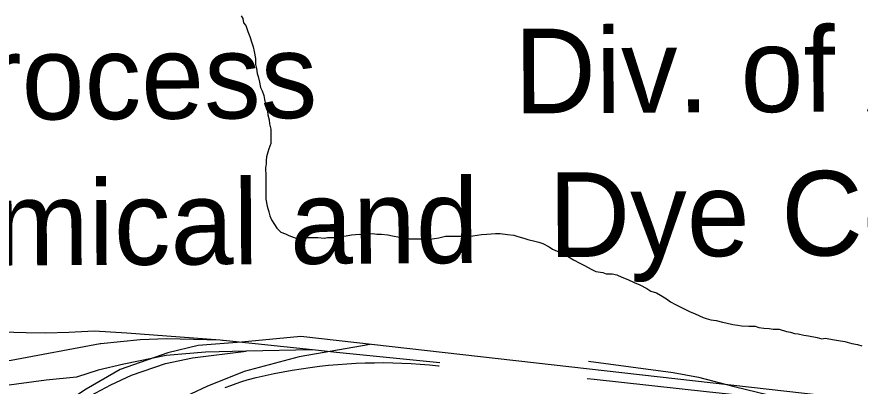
# Model space of a CAD drawing. Extents: x 3313442 to 3351311, y 721974 to 747360.
# Drawn here: x 3326114 to 3326941, y 728065 to 728427 of the extents above; entities that cross this region are included whole.
import ezdxf

# ---------------------------------------------------------------- set-up
doc = ezdxf.new("R2010")
doc.units = 0
for name, color, linetype in [('V-BLDG-IDEN', 7, 'Continuous'), ('V-RAIL-TRAK', 7, 'Continuous'), ('V-ROAD-CNTR', 7, 'Continuous'), ('V-TOPO-SHOR', 7, 'Continuous')]:
    doc.layers.add(name, color=color, linetype=linetype)

msp = doc.modelspace()

# ---------------------------------------------------------------- linework, layer by layer
at = {"layer": 'V-RAIL-TRAK'}
msp.add_line((3326404.1, 728100.63), (3326319.87, 728109.55), dxfattribs=at)
for points in [[(3326319.87, 728109.55), (3326313.59, 728110.02), (3326222.22, 728116.89), (3326206.08, 728118.08), (3326189.94, 728118.85), (3326165.29, 728117.63), (3326142.72, 728117.02), (3326123.27, 728117.41), (3326050.82, 728119.13), (3325836.27, 728133.16), (3325592.99, 728152.23)], [(3326195.84, 728106.45), (3326108.53, 728090.3), (3326083.03, 728087.43), (3326066.88, 728086.55), (3326035.01, 728088.09), (3325588.6, 728124.6)], [(3326319.87, 728109.55), (3326315.96, 728109.96), (3326313.59, 728110.02), (3326261.32, 728111.31), (3326235.02, 728110.52), (3326196.68, 728106.53), (3326195.84, 728106.45)], [(3326404.1, 728100.63), (3326339.26, 728099.19), (3326299.33, 728098.31), (3326260.79, 728094.95), (3326219.29, 728086.46), (3326193.82, 728080.84), (3326172.6, 728073.8), (3326142.89, 728071.02), (3326101.86, 728065.42), (3326053.88, 728061.48), (3325992.83, 728064.54), (3325858.65, 728073.07), (3325585.99, 728094.07)], [(3325985.79, 727363.24), (3326009.02, 727591.42), (3326017.46, 727674.76), (3326022.43, 727718.19), (3326022.46, 727718.49), (3326028.56, 727775.9), (3326035.27, 727828.42), (3326038.78, 727849.29), (3326044.81, 727873.66), (3326053.97, 727900.91), (3326066.03, 727928.53), (3326075.5, 727945.01), (3326093.14, 727971.34), (3326115.75, 727997.83), (3326128.71, 728011.17), (3326153.98, 728034.11), (3326177.11, 728050.67), (3326206.24, 728066.33), (3326226.62, 728075.66), (3326260.06, 728087.15), (3326286.4, 728092.69), (3326339.26, 728099.19)], [(3326528.99, 728087.87), (3326427.65, 728098.14), (3326404.1, 728100.63)], [(3326674.99, 728089.54), (3326716.53, 728084.02), (3326757.88, 728078.31), (3326782.9, 728073.71), (3326817.76, 728064.83), (3326851.67, 728056.54), (3326877.05, 728050.35)], [(3326340.13, 728071.24), (3326348.88, 728073.45), (3326357.66, 728075.5), (3326366.47, 728077.4), (3326375.32, 728079.15), (3326384.2, 728080.74), (3326393.1, 728082.17), (3326402.02, 728083.45), (3326410.97, 728084.58), (3326419.94, 728085.54), (3326428.92, 728086.35), (3326437.91, 728087.01), (3326446.92, 728087.51), (3326455.93, 728087.85), (3326464.94, 728088.03), (3326473.96, 728088.06), (3326482.97, 728087.92), (3326491.99, 728087.63), (3326500.99, 728087.19), (3326509.99, 728086.58), (3326518.98, 728085.82), (3326527.95, 728084.9), (3326528.45, 728084.85)], [(3326318.62, 728063.56), (3326324.04, 728065.66), (3326329.5, 728067.66), (3326335, 728069.56), (3326340.13, 728071.24)], [(3326983.36, 728039.07), (3326877.05, 728050.35), (3326790.61, 728059.52), (3326680.58, 728071.53), (3326673.55, 728072.22)]]:
    msp.add_lwpolyline(points, dxfattribs=at)
at = {"layer": 'V-ROAD-CNTR'}
for points in [[(3327025.43, 728042.18), (3326392.8, 728113.66), (3326334.7, 728108.13), (3326292.14, 728104.74), (3326262.39, 728097.61), (3326215.45, 728081.43), (3326182.31, 728062.11), (3326160.18, 728047.83), (3326133.05, 728026.27), (3326105.61, 727995.37), (3326076.21, 727955.76), (3326065.98, 727932.84), (3326051.28, 727900.09), (3326042.13, 727864.83), (3326032.84, 727808.33), (3326009.58, 727586.2), (3325984.72, 727366.08)], [(3326460.83, 728105.98), (3326391.24, 728093.81), (3326337.19, 728079.55), (3326300.61, 728064.57), (3326254.46, 728043.15), (3326225.23, 728021.97), (3326192.21, 727991.97), (3326160.52, 727958.01), (3326125.37, 727903.1), (3326110.13, 727866.88), (3326095.45, 727827.5), (3326093.16, 727766.49), (3326082.4, 727675.66), (3326045.28, 727366.17)]]:
    msp.add_lwpolyline(points, dxfattribs=at)
at = {"layer": 'V-TOPO-SHOR'}
for points in [[(3326334.17, 728428.44), (3326335.86, 728425.59), (3326336.41, 728421.62), (3326338.67, 728418.78), (3326339.8, 728415.93), (3326340.92, 728413.09), (3326342.61, 728407.98), (3326344.85, 728401.73), (3326345.98, 728397.76), (3326347.09, 728393.21), (3326348.21, 728386.4), (3326348.19, 728380.73), (3326349.31, 728376.76), (3326349.86, 728371.65), (3326350.98, 728368.81), (3326352.09, 728363.13), (3326353.21, 728358.02), (3326354.9, 728354.61), (3326356.59, 728350.07), (3326357.14, 728346.09), (3326358.26, 728341.55), (3326358.82, 728337.58), (3326359.94, 728334.74), (3326360.5, 728331.33), (3326361.61, 728326.22), (3326362.17, 728322.25), (3326363.29, 728317.14), (3326363.27, 728312.6), (3326363.25, 728307.49), (3326363.23, 728302.95), (3326361.52, 728297.85), (3326360.37, 728294.45), (3326359.22, 728289.92), (3326358.64, 728286.52), (3326358.63, 728283.11), (3326358.05, 728279.14), (3326358.59, 728271.2), (3326358.57, 728265.53), (3326358.54, 728257.02), (3326358.52, 728251.91), (3326358.51, 728248.51), (3326359.62, 728241.69), (3326361.3, 728236.02), (3326362.42, 728232.04), (3326364.11, 728228.06), (3326366.93, 728223.51), (3326369.19, 728220.1), (3326373.15, 728216.12), (3326377.68, 728214.4), (3326381.08, 728212.68)], [(3326381.08, 728212.68), (3326386.18, 728210.97), (3326389.01, 728209.82), (3326394.12, 728210.37), (3326398.09, 728210.93), (3326403.77, 728210.9), (3326409.44, 728210.89), (3326415.68, 728210.3), (3326419.08, 728210.85), (3326425.89, 728210.83), (3326430.43, 728211.38), (3326437.24, 728212.49), (3326442.35, 728213.61), (3326450.3, 728214.15), (3326453.7, 728213.57), (3326458.24, 728214.12), (3326463.35, 728214.67), (3326467.32, 728214.09), (3326471.86, 728214.08), (3326478.1, 728213.48), (3326482.63, 728212.33), (3326489.44, 728211.18), (3326493.4, 728210.59), (3326499.07, 728209.44), (3326503.61, 728209.43), (3326508.15, 728209.41), (3326513.83, 728209.39), (3326519.5, 728209.37), (3326528.01, 728210.48), (3326534.83, 728212.16), (3326540.5, 728212.14), (3326546.74, 728212.11), (3326550.71, 728212.1), (3326556.95, 728212.08), (3326561.49, 728212.63), (3326570.01, 728213.73), (3326575.11, 728214.29)], [(3326575.11, 728214.29), (3326583.62, 728214.82), (3326588.17, 728214.81), (3326595.54, 728213.65), (3326601.77, 728213.06), (3326605.74, 728211.91), (3326611.41, 728210.19), (3326615.38, 728209.04), (3326622.18, 728207.31), (3326626.15, 728206.17), (3326630.11, 728205.02), (3326636.34, 728201.59), (3326639.74, 728199.31), (3326646.54, 728196.45), (3326649.37, 728194.74), (3326654.46, 728192.45), (3326660.13, 728189.03), (3326666.36, 728185.6), (3326670.89, 728183.32), (3326677.68, 728179.89), (3326682.21, 728177.61), (3326689.02, 728176.45), (3326692.42, 728175.3), (3326698.09, 728175.28), (3326702.63, 728174.13), (3326707.72, 728171.84), (3326713.39, 728169.56), (3326719.62, 728166.7), (3326725.29, 728164.41), (3326732.08, 728160.98), (3326736.04, 728158.13), (3326741.71, 728156.41), (3326745.68, 728154.13), (3326751.34, 728150.7), (3326755.3, 728147.85), (3326760.39, 728145), (3326764.36, 728143.28), (3326769.46, 728140.43), (3326773.99, 728138.14), (3326779.65, 728135.85), (3326787.58, 728132.42), (3326790.42, 728131.28), (3326794.95, 728130.13), (3326800.05, 728129.54), (3326806.29, 728127.82), (3326809.69, 728127.24), (3326816.49, 728125.52), (3326821.6, 728124.93), (3326825, 728124.35), (3326832.37, 728123.76), (3326838.61, 728123.74), (3326842.02, 728122.59), (3326847.12, 728122.01), (3326852.22, 728121.42), (3326856.19, 728120.84), (3326861.86, 728120.82), (3326869.23, 728118.53), (3326873.2, 728117.95), (3326877.17, 728116.8), (3326880.57, 728116.22), (3326886.24, 728115.06), (3326890.78, 728114.48), (3326899.28, 728112.75), (3326903.81, 728111.6), (3326907.22, 728112.15)], [(3326907.22, 728112.15), (3326916.29, 728110.42), (3326920.26, 728109.84), (3326926.5, 728108.68), (3326933.3, 728106.96), (3326938.97, 728105.8), (3326942.94, 728104.65)]]:
    msp.add_lwpolyline(points, dxfattribs=at)

# ---------------------------------------------------------------- texts
at = {"layer": 'V-BLDG-IDEN'}
for s, height, p in [('Div. of Allied', 82.9998, (3326602.33, 728332.57)), ('Solvay Process', 82.9998, (3325644.16, 728323.91)), ('Chemical and', 82.9998, (3325888.92, 728182.17)), ('Dye Corp.', 83, (3326635.95, 728191.62))]:
    msp.add_text(s, height=height, rotation=0.31789, dxfattribs=at).set_placement(p)

doc.saveas('drawing.dxf')
